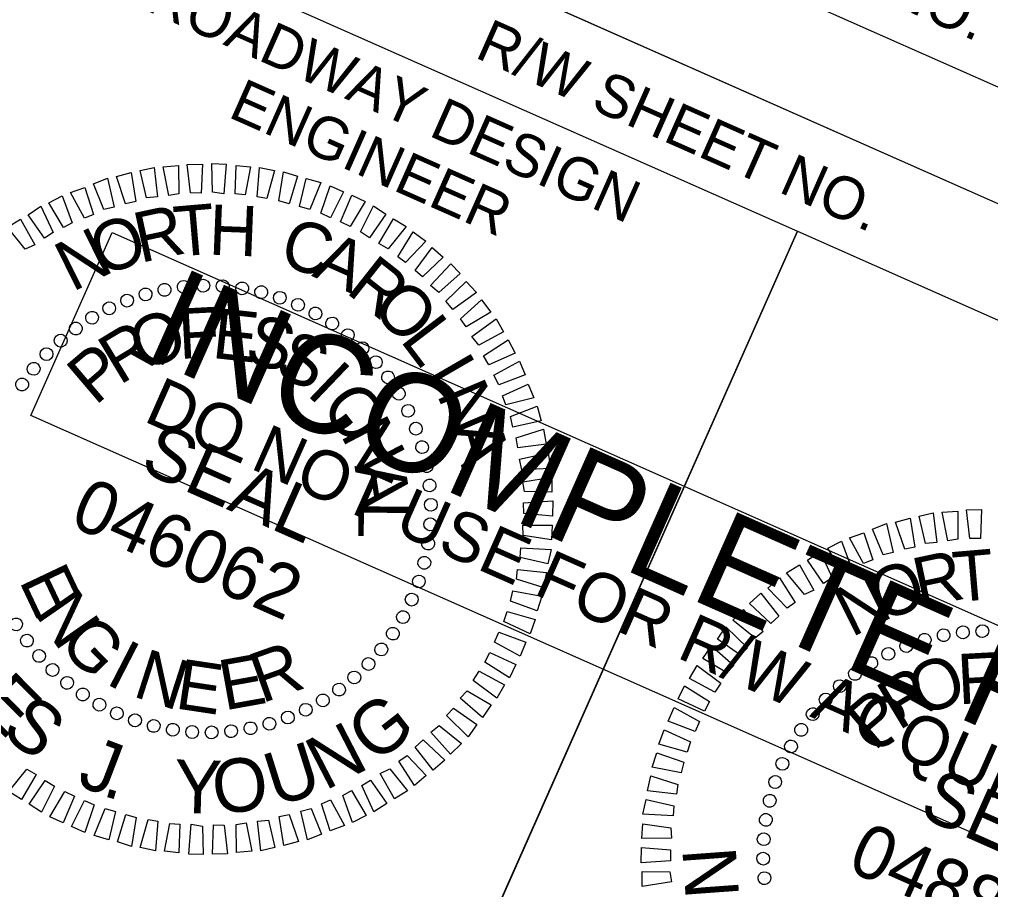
# Model space of a CAD drawing. Extents: x 1638962 to 2864602, y 841929 to 973236.
# Drawn here: x 1640722.4 to 1640836.4, y 842844.8 to 842947 of the extents above; entities that cross this region are included whole.
import ezdxf

# ---------------------------------------------------------------- set-up
doc = ezdxf.new("R2010")
doc.units = 0
for name, color, linetype in [('Default', 7, 'Continuous'), ('DEV STATIONARY SIGN DUAL MOUNT CELL', 7, 'Continuous'), ('Old_Level_2', 7, 'Continuous'), ('Prop Conc Curb and Gutter', 7, 'Continuous'), ('Scratch_Level_5', 7, 'Continuous')]:
    doc.layers.add(name, color=color, linetype=linetype)

msp = doc.modelspace()

# ---------------------------------------------------------------- linework, layer by layer
at = {"layer": 'DEV STATIONARY SIGN DUAL MOUNT CELL'}
for p, q in [((1640732.38, 842985.57), (1640915.25, 842904.47)), ((1640727.3, 842974.1), (1640910.18, 842893.04)), ((1640727.3, 842974.1), (1640910.18, 842893.04)), ((1640813.7, 842922.13), (1640768.13, 842819.32))]:
    msp.add_line(p, q, dxfattribs=at)
for points in [[(1640737.47, 842997.04), (1640920.37, 842915.92), (1640910.18, 842893.04), (1640727.3, 842974.1)], [(1640722.24, 842962.69), (1640813.7, 842922.13), (1640768.1, 842819.28), (1640676.66, 842859.85)], [(1640813.7, 842922.13), (1640905.11, 842881.61), (1640859.52, 842778.75), (1640768.1, 842819.28)]]:
    msp.add_lwpolyline(points, close=True, dxfattribs=at)
at = {"layer": 'Old_Level_2'}
for p, q in [((1640739.38, 842915.28), (1640739.38, 842915.28)), ((1640741.68, 842915.61), (1640741.68, 842915.61)), ((1640743.96, 842915.78), (1640743.96, 842915.78)), ((1640746.21, 842915.74), (1640746.21, 842915.74)), ((1640748.48, 842915.46), (1640748.48, 842915.46)), ((1640734.98, 842914.01), (1640734.98, 842914.01)), ((1640737.18, 842914.78), (1640737.18, 842914.78)), ((1640750.76, 842914.95), (1640750.76, 842914.95)), ((1640752.96, 842914.36), (1640752.96, 842914.36)), ((1640732.91, 842913.13), (1640732.91, 842913.13)), ((1640755.1, 842913.51), (1640755.1, 842913.51)), ((1640730.89, 842911.99), (1640730.89, 842911.99)), ((1640757.15, 842912.47), (1640757.15, 842912.47)), ((1640728.96, 842910.77), (1640728.96, 842910.77)), ((1640759.08, 842911.26), (1640759.08, 842911.26)), ((1640727.2, 842909.3), (1640727.2, 842909.3)), ((1640760.92, 842909.97), (1640760.92, 842909.97)), ((1640762.66, 842908.44), (1640762.66, 842908.44)), ((1640725.52, 842907.74), (1640725.52, 842907.74)), ((1640723.99, 842906), (1640723.99, 842906)), ((1640764.22, 842906.76), (1640764.22, 842906.76)), ((1640765.69, 842905.01), (1640765.69, 842905.01)), ((1640722.7, 842904.16), (1640722.7, 842904.16)), ((1640766.92, 842903.07), (1640766.92, 842903.07)), ((1640768.05, 842901.06), (1640768.05, 842901.06)), ((1640768.93, 842898.98), (1640768.93, 842898.98)), ((1640769.71, 842896.78), (1640769.71, 842896.78)), ((1640770.2, 842894.58), (1640770.2, 842894.58)), ((1640770.53, 842892.29), (1640770.53, 842892.29)), ((1640770.7, 842890), (1640770.7, 842890)), ((1640744.44, 842889.52), (1640744.44, 842889.52)), ((1640770.66, 842887.75), (1640770.66, 842887.75)), ((1640770.38, 842885.48), (1640770.38, 842885.48)), ((1640769.87, 842883.2), (1640769.87, 842883.2)), ((1640769.29, 842881.01), (1640769.29, 842881.01)), ((1640768.44, 842878.87), (1640768.44, 842878.87)), ((1640767.4, 842876.81), (1640767.4, 842876.81)), ((1640835.42, 842875.23), (1640835.42, 842875.23)), ((1640723.2, 842874.03), (1640723.2, 842874.03)), ((1640766.19, 842874.88), (1640766.19, 842874.88)), ((1640828.64, 842874.23), (1640828.64, 842874.23)), ((1640830.84, 842874.72), (1640830.84, 842874.72)), ((1640833.14, 842875.06), (1640833.14, 842875.06)), ((1640764.9, 842873.04), (1640764.9, 842873.04)), ((1640826.44, 842873.46), (1640826.44, 842873.46)), ((1640724.67, 842872.28), (1640724.67, 842872.28)), ((1640824.37, 842872.58), (1640824.37, 842872.58)), ((1640726.23, 842870.6), (1640726.23, 842870.6)), ((1640763.37, 842871.3), (1640763.37, 842871.3)), ((1640822.35, 842871.44), (1640822.35, 842871.44)), ((1640761.69, 842869.74), (1640761.69, 842869.74)), ((1640820.42, 842870.21), (1640820.42, 842870.21)), ((1640727.96, 842869.07), (1640727.96, 842869.07)), ((1640759.93, 842868.27), (1640759.93, 842868.27)), ((1640818.66, 842868.74), (1640818.66, 842868.74)), ((1640729.8, 842867.78), (1640729.8, 842867.78)), ((1640816.98, 842867.18), (1640816.98, 842867.18)), ((1640731.73, 842866.57), (1640731.73, 842866.57)), ((1640757.99, 842867.05), (1640757.99, 842867.05)), ((1640733.79, 842865.53), (1640733.79, 842865.53)), ((1640753.9, 842865.03), (1640753.9, 842865.03)), ((1640755.98, 842865.91), (1640755.98, 842865.91)), ((1640815.45, 842865.45), (1640815.45, 842865.45)), ((1640735.93, 842864.68), (1640735.93, 842864.68)), ((1640738.12, 842864.09), (1640738.12, 842864.09)), ((1640749.51, 842863.76), (1640749.51, 842863.76)), ((1640751.7, 842864.26), (1640751.7, 842864.26)), ((1640740.41, 842863.58), (1640740.41, 842863.58)), ((1640742.67, 842863.3), (1640742.67, 842863.3)), ((1640744.92, 842863.26), (1640744.92, 842863.26)), ((1640747.21, 842863.43), (1640747.21, 842863.43)), ((1640814.16, 842863.61), (1640814.16, 842863.61)), ((1640812.95, 842861.68), (1640812.95, 842861.68)), ((1640811.91, 842859.62), (1640811.91, 842859.62)), ((1640811.06, 842857.48), (1640811.06, 842857.48)), ((1640810.47, 842855.29), (1640810.47, 842855.29)), ((1640809.96, 842853), (1640809.96, 842853)), ((1640809.69, 842850.74), (1640809.69, 842850.74)), ((1640835.9, 842848.97), (1640835.9, 842848.97)), ((1640809.64, 842848.48), (1640809.64, 842848.48)), ((1640809.81, 842846.2), (1640809.81, 842846.2))]:
    msp.add_line(p, q, dxfattribs=at)
for points in [[(1640739.91, 842926.35), (1640739.23, 842929.7), (1640741.05, 842929.84), (1640741.07, 842926.54)], [(1640742.47, 842926.63), (1640742.07, 842929.98), (1640743.85, 842930.02), (1640743.72, 842926.61)], [(1640745.02, 842926.74), (1640744.95, 842930.07), (1640746.64, 842930.03), (1640746.35, 842926.52)], [(1640747.71, 842926.52), (1640747.82, 842929.87), (1640749.5, 842929.68), (1640748.86, 842926.43)], [(1640734.84, 842925.37), (1640733.75, 842928.55), (1640735.48, 842929.02), (1640736.02, 842925.61)], [(1640737.29, 842926.04), (1640736.54, 842929.25), (1640738.18, 842929.63), (1640738.59, 842926.17)], [(1640750.28, 842926.16), (1640750.55, 842929.63), (1640752.33, 842929.27), (1640751.4, 842925.98)], [(1640752.82, 842925.72), (1640753.35, 842929.13), (1640755, 842928.6), (1640754.03, 842925.37)], [(1640732.29, 842924.69), (1640731.06, 842927.7), (1640732.71, 842928.37), (1640733.49, 842924.98)], [(1640755.25, 842925.03), (1640756.02, 842928.34), (1640757.74, 842927.84), (1640756.47, 842924.68)], [(1640729.99, 842923.67), (1640728.36, 842926.69), (1640730.04, 842927.29), (1640731.08, 842924.12)], [(1640757.76, 842924.25), (1640758.84, 842927.48), (1640760.41, 842926.76), (1640758.9, 842923.72)], [(1640727.53, 842922.56), (1640725.82, 842925.49), (1640727.4, 842926.3), (1640728.57, 842923.14)], [(1640760.05, 842923.23), (1640761.38, 842926.36), (1640762.95, 842925.64), (1640761.19, 842922.69)], [(1640725.31, 842921.34), (1640723.4, 842924.07), (1640724.9, 842925.08), (1640726.32, 842921.99)], [(1640762.4, 842922.06), (1640763.92, 842925.11), (1640765.38, 842924.15), (1640763.47, 842921.38)], [(1640723.05, 842920.02), (1640720.96, 842922.61), (1640722.5, 842923.55), (1640724.19, 842920.56)], [(1640764.55, 842920.7), (1640766.29, 842923.6), (1640767.77, 842922.69), (1640765.64, 842920.07)], [(1640766.78, 842919.13), (1640768.59, 842922.06), (1640770.06, 842920.98), (1640767.69, 842918.47)], [(1640768.83, 842917.53), (1640770.81, 842920.21), (1640772.1, 842919.1), (1640769.7, 842916.77)], [(1640770.63, 842915.75), (1640773.02, 842918.31), (1640774.12, 842917.17), (1640771.59, 842914.94)], [(1640772.41, 842913.92), (1640774.82, 842916.25), (1640776.02, 842914.94), (1640773.25, 842912.94)], [(1640774.16, 842911.87), (1640776.62, 842914.07), (1640777.72, 842912.64), (1640774.83, 842910.91)], [(1640775.49, 842909.78), (1640778.35, 842911.86), (1640779.18, 842910.32), (1640776.3, 842908.75)], [(1640776.85, 842907.5), (1640779.75, 842909.39), (1640780.56, 842907.81), (1640777.48, 842906.44)], [(1640778.05, 842905.23), (1640781.08, 842906.9), (1640781.75, 842905.26), (1640778.66, 842904.12)], [(1640779.07, 842902.81), (1640782.1, 842904.2), (1640782.77, 842902.56), (1640779.47, 842901.74)], [(1640780.02, 842900.37), (1640783.15, 842901.6), (1640783.62, 842899.87), (1640780.29, 842899.12)], [(1640780.67, 842897.88), (1640783.89, 842898.9), (1640784.21, 842897.12), (1640780.87, 842896.72)], [(1640781.09, 842895.37), (1640784.42, 842896.12), (1640784.72, 842894.29), (1640781.36, 842894.13)], [(1640781.45, 842892.73), (1640784.86, 842893.27), (1640784.85, 842891.51), (1640781.64, 842891.57)], [(1640781.54, 842890.25), (1640784.99, 842890.49), (1640784.96, 842888.68), (1640781.57, 842888.98)], [(1640828.74, 842885.48), (1640828, 842888.69), (1640829.64, 842889.08), (1640830.05, 842885.61)], [(1640831.37, 842885.79), (1640830.69, 842889.15), (1640832.51, 842889.29), (1640832.53, 842885.98)], [(1640833.93, 842886.07), (1640833.53, 842889.42), (1640835.31, 842889.46), (1640835.18, 842886.06)], [(1640781.45, 842887.62), (1640784.91, 842887.63), (1640784.81, 842885.91), (1640781.5, 842886.4)], [(1640823.75, 842884.13), (1640822.52, 842887.15), (1640824.17, 842887.82), (1640824.95, 842884.42)], [(1640826.3, 842884.81), (1640825.21, 842888), (1640826.94, 842888.46), (1640827.48, 842885.05)], [(1640821.44, 842883.12), (1640819.82, 842886.13), (1640821.49, 842886.73), (1640822.54, 842883.57)], [(1640818.98, 842882), (1640817.27, 842884.94), (1640818.86, 842885.74), (1640820.03, 842882.58)], [(1640781.24, 842884.98), (1640784.79, 842884.78), (1640784.41, 842883.07), (1640781.15, 842883.83)], [(1640816.77, 842880.78), (1640814.86, 842883.52), (1640816.36, 842884.53), (1640817.78, 842881.43)], [(1640780.84, 842882.42), (1640784.26, 842882.06), (1640783.86, 842880.3), (1640780.7, 842881.29)], [(1640814.51, 842879.47), (1640812.42, 842882.05), (1640813.95, 842882.99), (1640815.64, 842880.01)], [(1640812.48, 842877.88), (1640810.24, 842880.25), (1640811.59, 842881.44), (1640813.44, 842878.56)], [(1640780.3, 842879.93), (1640783.71, 842879.28), (1640783.16, 842877.58), (1640780, 842878.69)], [(1640810.58, 842876.08), (1640808.06, 842878.45), (1640809.41, 842879.63), (1640811.51, 842876.93)], [(1640779.61, 842877.49), (1640782.9, 842876.56), (1640782.31, 842874.88), (1640779.22, 842876.3)], [(1640808.72, 842874.36), (1640806.1, 842876.49), (1640807.35, 842877.72), (1640809.67, 842875.15)], [(1640807.02, 842872.36), (1640804.3, 842874.25), (1640805.31, 842875.69), (1640807.83, 842873.21)], [(1640778.64, 842875.07), (1640781.83, 842873.89), (1640781.14, 842872.25), (1640778.15, 842873.91)], [(1640805.41, 842870.31), (1640802.59, 842871.96), (1640803.62, 842873.45), (1640806.23, 842871.16)], [(1640777.57, 842872.68), (1640780.66, 842871.26), (1640779.89, 842869.71), (1640776.99, 842871.56)], [(1640803.99, 842868.02), (1640801.03, 842869.61), (1640801.92, 842871.17), (1640804.72, 842869.07)], [(1640776.35, 842870.47), (1640779.32, 842868.88), (1640778.43, 842867.32), (1640775.63, 842869.41)], [(1640802.77, 842865.81), (1640799.68, 842867.23), (1640800.45, 842868.78), (1640803.36, 842866.92)], [(1640774.93, 842868.17), (1640777.75, 842866.53), (1640776.73, 842865.03), (1640774.12, 842867.33)], [(1640773.33, 842866.13), (1640776.05, 842864.24), (1640775.04, 842862.79), (1640772.52, 842865.28)], [(1640801.71, 842863.42), (1640798.52, 842864.6), (1640799.21, 842866.24), (1640802.2, 842864.58)], [(1640771.63, 842864.12), (1640774.25, 842861.99), (1640772.99, 842860.76), (1640770.67, 842863.33)], [(1640800.74, 842860.99), (1640797.44, 842861.93), (1640798.04, 842863.61), (1640801.13, 842862.19)], [(1640769.77, 842862.41), (1640772.29, 842860.04), (1640770.93, 842858.85), (1640768.84, 842861.55)], [(1640767.87, 842860.6), (1640770.11, 842858.24), (1640768.75, 842857.05), (1640766.9, 842859.93)], [(1640800.05, 842858.56), (1640796.63, 842859.21), (1640797.18, 842860.9), (1640800.35, 842859.79)], [(1640724.34, 842858.34), (1640722.6, 842855.44), (1640721.11, 842856.35), (1640723.24, 842858.97)], [(1640765.84, 842859.02), (1640767.92, 842856.43), (1640766.39, 842855.49), (1640764.7, 842858.48)], [(1640799.51, 842856.06), (1640796.08, 842856.43), (1640796.49, 842858.19), (1640799.64, 842857.2)], [(1640726.49, 842856.98), (1640724.97, 842853.93), (1640723.5, 842854.89), (1640725.41, 842857.66)], [(1640763.58, 842857.7), (1640765.49, 842854.97), (1640763.98, 842853.96), (1640762.57, 842857.05)], [(1640728.83, 842855.81), (1640727.51, 842852.68), (1640725.94, 842853.4), (1640727.7, 842856.35)], [(1640761.36, 842856.48), (1640763.07, 842853.55), (1640761.48, 842852.74), (1640760.32, 842855.9)], [(1640731.13, 842854.79), (1640730.04, 842851.56), (1640728.47, 842852.27), (1640729.99, 842855.32)], [(1640758.9, 842855.37), (1640760.52, 842852.35), (1640758.85, 842851.75), (1640757.81, 842854.92)], [(1640799.11, 842853.51), (1640795.56, 842853.7), (1640795.94, 842855.41), (1640799.2, 842854.66)], [(1640733.64, 842854.01), (1640732.86, 842850.7), (1640731.14, 842851.2), (1640732.42, 842854.35)], [(1640736.07, 842853.32), (1640735.54, 842849.91), (1640733.89, 842850.44), (1640734.85, 842853.67)], [(1640754.04, 842853.67), (1640755.14, 842850.49), (1640753.41, 842850.02), (1640752.86, 842853.43)], [(1640756.6, 842854.35), (1640757.82, 842851.34), (1640756.18, 842850.67), (1640755.4, 842854.06)], [(1640738.6, 842852.87), (1640738.33, 842849.41), (1640736.55, 842849.77), (1640737.49, 842853.06)], [(1640741.18, 842852.52), (1640741.07, 842849.17), (1640739.39, 842849.36), (1640740.03, 842852.61)], [(1640743.87, 842852.3), (1640743.94, 842848.97), (1640742.25, 842849.01), (1640742.54, 842852.52)], [(1640746.41, 842852.41), (1640746.81, 842849.06), (1640745.04, 842849.02), (1640745.17, 842852.43)], [(1640748.97, 842852.69), (1640749.66, 842849.34), (1640747.84, 842849.2), (1640747.81, 842852.5)], [(1640751.6, 842853), (1640752.34, 842849.79), (1640750.71, 842849.41), (1640750.3, 842852.87)], [(1640798.9, 842850.87), (1640795.43, 842850.86), (1640795.53, 842852.58), (1640798.85, 842852.08)], [(1640798.81, 842848.24), (1640795.36, 842847.99), (1640795.38, 842849.8), (1640798.78, 842849.5)], [(1640798.9, 842845.76), (1640795.49, 842845.21), (1640795.49, 842846.97), (1640798.71, 842846.92)]]:
    msp.add_lwpolyline(points, close=True, dxfattribs=at)
for centre, major_axis in [((1640741.66, 842915.6), (-0.08, 0.749)), ((1640743.95, 842915.74), (-0.014, 0.753)), ((1640746.23, 842915.69), (0.051, 0.751)), ((1640748.51, 842915.43), (0.117, 0.744)), ((1640737.18, 842914.72), (-0.209, 0.723)), ((1640739.4, 842915.26), (-0.145, 0.739)), ((1640750.75, 842914.98), (0.181, 0.731)), ((1640752.94, 842914.33), (0.244, 0.712)), ((1640732.91, 842913.08), (-0.331, 0.676)), ((1640735.01, 842913.99), (-0.271, 0.703)), ((1640755.07, 842913.5), (0.305, 0.688)), ((1640730.9, 842911.98), (-0.389, 0.645)), ((1640757.12, 842912.48), (0.364, 0.659)), ((1640728.99, 842910.71), (-0.443, 0.608)), ((1640759.08, 842911.29), (0.42, 0.625)), ((1640760.92, 842909.93), (0.473, 0.586)), ((1640727.21, 842909.29), (-0.495, 0.568)), ((1640725.55, 842907.71), (-0.542, 0.522)), ((1640762.63, 842908.41), (0.522, 0.542)), ((1640764.21, 842906.76), (0.568, 0.495)), ((1640724.04, 842905.99), (-0.586, 0.473)), ((1640722.68, 842904.15), (-0.625, 0.42)), ((1640765.64, 842904.97), (0.608, 0.443)), ((1640766.9, 842903.06), (0.645, 0.389)), ((1640768, 842901.05), (0.676, 0.331)), ((1640768.91, 842898.96), (0.703, 0.271)), ((1640769.64, 842896.79), (0.723, 0.209)), ((1640770.18, 842894.56), (0.739, 0.145)), ((1640770.52, 842892.3), (0.749, 0.08)), ((1640770.67, 842890.02), (0.753, 0.014)), ((1640770.61, 842887.73), (0.751, -0.051)), ((1640770.35, 842885.46), (0.744, -0.117)), ((1640769.9, 842883.21), (0.731, -0.181)), ((1640769.26, 842881.02), (0.712, -0.244)), ((1640768.42, 842878.89), (0.688, -0.305)), ((1640767.4, 842876.84), (0.659, -0.364)), ((1640721.98, 842875.98), (-0.645, -0.389)), ((1640766.21, 842874.89), (0.625, -0.42)), ((1640830.86, 842874.7), (-0.145, 0.739)), ((1640833.12, 842875.05), (-0.08, 0.749)), ((1640835.4, 842875.19), (-0.014, 0.753)), ((1640723.25, 842874.07), (-0.608, -0.443)), ((1640826.47, 842873.44), (-0.271, 0.703)), ((1640828.63, 842874.17), (-0.209, 0.723)), ((1640724.68, 842872.28), (-0.568, -0.495)), ((1640764.85, 842873.04), (0.586, -0.473)), ((1640824.37, 842872.52), (-0.331, 0.676)), ((1640763.34, 842871.33), (0.542, -0.522)), ((1640822.36, 842871.43), (-0.389, 0.645)), ((1640726.25, 842870.63), (-0.522, -0.542)), ((1640761.68, 842869.75), (0.495, -0.568)), ((1640820.45, 842870.16), (-0.443, 0.608)), ((1640727.97, 842869.11), (-0.473, -0.586)), ((1640818.67, 842868.73), (-0.495, 0.568)), ((1640729.81, 842867.75), (-0.42, -0.625)), ((1640759.89, 842868.32), (0.443, -0.608)), ((1640731.76, 842866.56), (-0.364, -0.659)), ((1640757.99, 842867.06), (0.389, -0.645)), ((1640817.01, 842867.16), (-0.542, 0.522)), ((1640733.81, 842865.54), (-0.305, -0.688)), ((1640755.98, 842865.96), (0.331, -0.676)), ((1640815.49, 842865.44), (-0.586, 0.473)), ((1640735.94, 842864.71), (-0.244, -0.712)), ((1640738.14, 842864.06), (-0.181, -0.731)), ((1640751.71, 842864.32), (0.209, -0.723)), ((1640753.88, 842865.05), (0.271, -0.703)), ((1640740.38, 842863.61), (-0.117, -0.744)), ((1640742.65, 842863.35), (-0.051, -0.751)), ((1640744.94, 842863.3), (0.014, -0.753)), ((1640747.22, 842863.44), (0.08, -0.749)), ((1640749.49, 842863.78), (0.145, -0.739)), ((1640814.14, 842863.6), (-0.625, 0.42)), ((1640812.94, 842861.65), (-0.659, 0.364)), ((1640811.93, 842859.6), (-0.688, 0.305)), ((1640811.09, 842857.47), (-0.712, 0.244)), ((1640810.44, 842855.27), (-0.731, 0.181)), ((1640809.99, 842853.03), (-0.744, 0.117)), ((1640809.74, 842850.76), (-0.751, 0.051)), ((1640809.68, 842848.47), (-0.753, -0.014)), ((1640809.82, 842846.18), (-0.749, -0.08))]:
    msp.add_ellipse(centre, major_axis=major_axis, ratio=0.999708, dxfattribs=at)
at = {"layer": 'Prop Conc Curb and Gutter'}
msp.add_lwpolyline([(1640723.71, 842900.5), (1640733.24, 842921.99), (1640867.62, 842862.4), (1640858.1, 842840.92)], close=True, dxfattribs=at)

# ---------------------------------------------------------------- texts
at = {"layer": 'Default'}
for s, rotation, p in [('E', 314.8396, (1640717.03, 842866.39)), ('S', 321.8463, (1640720.05, 842863.22)), ('G', 37.8869, (1640764.07, 842859.49)), ('N', 27.316, (1640758.23, 842856.4)), ('J', 339.1192, (1640728.96, 842857.16)), ('U', 17.5219, (1640752.4, 842854.54)), ('O', 6.1284, (1640745.33, 842853.66)), ('Y', 358.3297, (1640740.46, 842853.87)), ('.', 344.3011, (1640731.94, 842855.9)), ('N', 274.1644, (1640800.17, 842849.61))]:
    msp.add_text(s, height=6.27, rotation=rotation, dxfattribs=at).set_placement(p)
at = {"layer": 'DEV STATIONARY SIGN DUAL MOUNT CELL'}
for s, height, p in [('PROJECT REFERENCE NO.', 5.0001, (1640754.23, 842980.06)), ('ROADWAY DESIGN', 5.0001, (1640737, 842948.16)), ('R/W SHEET NO.', 5.0001, (1640775.69, 842942.6)), ('ENGINEER', 5, (1640746.73, 842935.6))]:
    msp.add_text(s, height=height, rotation=336.0871, dxfattribs=at).set_placement(p)
at = {"layer": 'Old_Level_2'}
for s, height, rotation, p in [('T', 5.9, 4.9069, (1640740.73, 842919.13)), ('H', 5.9, 357.7066, (1640744.53, 842919.4)), ('R', 5.9, 12.1076, (1640736.55, 842918.4)), ('O', 5.9, 19.3089, (1640731.97, 842916.82)), ('C', 5.9, 343.307, (1640752.66, 842918.23)), ('N', 5.9, 26.5106, (1640728.57, 842914.96)), ('A', 5.9, 336.1075, (1640756.59, 842916.91)), ('R', 5.9, 321.7082, (1640760.55, 842915.01)), ('O', 5.9, 314.5083, (1640763.48, 842912.92)), ('F', 5.9, 3.0542, (1640741.16, 842907.14)), ('E', 5.9, 353.6982, (1640744.86, 842907.28)), ('O', 5.9, 21.7684, (1640736.78, 842905.64)), ('S', 5.9, 344.3427, (1640748.61, 842906.89)), ('L', 5.9, 307.308, (1640766.96, 842909.35)), ('R', 5.9, 31.1268, (1640734.1, 842904)), ('S', 5.9, 334.9875, (1640752.09, 842905.47)), ('P', 5.9, 40.486, (1640731.26, 842901.57)), ('I', 5.9, 300.1073, (1640769.88, 842905.39)), ('I', 5.9, 316.2767, (1640755.95, 842903.05)), ('N', 5.9, 292.906, (1640771.32, 842903.02)), ('O', 5.9, 306.9206, (1640757.59, 842901.56)), ('N', 5.9, 297.5638, (1640760.01, 842898.27)), ('SEAL', 6.273, 336.0871, (1640736.33, 842894.09)), ('A', 5.9, 285.7043, (1640772.97, 842898.98)), ('A', 5.9, 278.8474, (1640761.69, 842894.6)), ('046062', 6.275, 336.0871, (1640728.05, 842887.69)), ('L', 5.9, 269.488, (1640762.17, 842890.49)), ('R', 5.9, 12.1076, (1640828.01, 842877.85)), ('T', 5.9, 4.9069, (1640832.18, 842878.58)), ('E', 5.9, 295.364, (1640722.27, 842881.12)), ('O', 5.9, 19.3089, (1640823.43, 842876.26)), ('N', 5.9, 26.5106, (1640820.03, 842874.41)), ('N', 5.9, 304.7211, (1640724.06, 842877.3)), ('G', 5.9, 314.0774, (1640726.81, 842873.59)), ('I', 5.9, 332.7883, (1640732.34, 842869.09)), ('N', 5.9, 342.1435, (1640735.51, 842867.58)), ('R', 5.9, 19.5685, (1640750.8, 842866.68)), ('E', 5.9, 351.4989, (1640740.52, 842866.14)), ('E', 5.9, 10.2112, (1640746.42, 842865.86)), ('O', 5.9, 21.7684, (1640828.24, 842865.09)), ('F', 5.9, 3.0542, (1640832.62, 842866.59)), ('R', 5.9, 31.1268, (1640825.56, 842863.44)), ('P', 5.9, 40.486, (1640822.71, 842861.01)), ('SEAL', 6.273, 336.0871, (1640827.78, 842853.53)), ('048883', 6.275, 336.0871, (1640819.32, 842847.22))]:
    msp.add_text(s, height=height, rotation=rotation, dxfattribs=at).set_placement(p)
at = {"layer": 'Prop Conc Curb and Gutter'}
for s, height, p in [('INCOMPLETE PLANS', 11.52, (1640736.64, 842907.57)), ('DO NOT USE FOR R/W ACQUISITION', 5.76, (1640736.79, 842899.9))]:
    msp.add_text(s, height=height, rotation=336.0871, dxfattribs=at).set_placement(p)
at = {"layer": 'Scratch_Level_5'}
msp.add_text('DOCUMENT NOT CONSIDERED FINAL', height=5.5, rotation=336.0871, dxfattribs=at).set_placement((1640691.73, 842841.85))
msp.add_text('DOCUMENT NOT CONSIDERED FINAL', height=5.5, rotation=336.0871, dxfattribs=at).set_placement((1640691.73, 842841.85))

doc.saveas('drawing.dxf')
